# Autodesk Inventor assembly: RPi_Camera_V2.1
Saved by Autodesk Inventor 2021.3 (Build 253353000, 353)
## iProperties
Created: 2023-02
Part Number: RPi_Camera_V2.1
Document SubType Name: Assembly
Designer: AdminForWorker
Title: RPi_Camera_V2.1 v1
Author: AdminForWorker
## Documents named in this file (5)
- z:\worker\convert-fusion-r08-cosv3\tmp\job-1\96\output\files\43403b88-af5f-43e8-9cd7-c20dddf799d9\1f80cf95-900f-4075-8c7f-ebcd5542d9e0.iam
- z:\worker\convert-fusion-r08-cosv3\tmp\job-1\96\output\files\43403b88-af5f-43e8-9cd7-c20dddf799d9\PCB.ipt
- z:\worker\convert-fusion-r08-cosv3\tmp\job-1\96\output\files\43403b88-af5f-43e8-9cd7-c20dddf799d9\Zif Connector.ipt
- z:\worker\convert-fusion-r08-cosv3\tmp\job-1\96\output\files\43403b88-af5f-43e8-9cd7-c20dddf799d9\Camera Lense.ipt
- z:\worker\convert-fusion-r08-cosv3\tmp\job-1\96\output\files\43403b88-af5f-43e8-9cd7-c20dddf799d9\Camera PCB connector.ipt
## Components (4 placed, 4 different names)
1. PCB:1
2. Zif Connector:1
3. Camera Lense:1
4. Camera PCB connector:1
